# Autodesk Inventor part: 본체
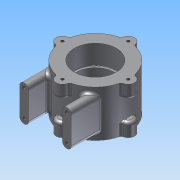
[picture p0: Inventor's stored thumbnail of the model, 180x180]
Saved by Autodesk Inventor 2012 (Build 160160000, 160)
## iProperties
Created: 2015-03
Part Number: 본체
Material: Default
Document SubType Name: Modeling
Designer: net
Density: 1 g/cm^3
Author: net
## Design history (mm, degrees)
sketch "스케치1"
  geometry: C1 r 37 at (0, 0); 1 further point
  constraints: 1 centre point, 1 coincident
  dimensions: "d0" = 74 diameter of C1
extrude "돌출1" new body sketch "스케치1" distance "d1" = 52; taper "d2" = 0 deg
sketch "스케치2"
  geometry: C1 r 7 at (0, 37); C2 r 7 at (-37, 0); C3 r 7 at (0, -37); C4 r 7 at (37, 0); 1 further point
  constraints: 4 centre point, 2 vertical alignment, 10 other
  dimensions: "d3" = 14 diameter of C1; "d6" = 360 deg dimension on point (0, 0) C1.centre (derived)
extrude "돌출2" join sketch "스케치2" distance "d8" = 15; taper "d9" = 0 deg
node "작업 평면1"
hole "구멍1" diameter "d12" = 42; stored, may be unused: countersink angle "d16" = 90 deg, drill point angle "d18" = 118 deg; dims "d10" = 10, "d11" = 10, "d13" = 6, "d14" = 47, "d15" = 22, "d17" = 8
hole "구멍2" diameter "d21" = 42; stored, may be unused: countersink angle "d25" = 90 deg, drill point angle "d27" = 118 deg; dims "d19" = 10, "d20" = 10, "d22" = 6, "d23" = 47, "d24" = 22, "d26" = 8
node "작업 평면2"
sketch "스케치4"
  geometry: L1 (6.969, 15)-(6.969, 0) reference; L2 (36.338, 0)-(6.969, 0) reference; L3 (36.338, 0)-(36.338, 15) reference; L4 (36.338, 15)-(36.338, 15) reference; L5 (36.338, 15)-(36.338, 0) reference; L6 (6.969, 0)-(36.338, 0) reference; L7 (6.969, 0)-(6.969, 15) reference; L8 (6.969, 15)-(-6.969, 15) reference; L9 (-6.969, 15)-(-6.969, 0) reference; L10 (-36.338, 0)-(-6.969, 0) reference; L11 (-36.338, 0)-(-36.338, 15) reference; L12 (-36.338, 15)-(-36.338, 15) reference; L13 (-36.338, 15)-(-36.338, 0) reference; L14 (-6.969, 0)-(-36.338, 0) reference; L15 (-6.969, 0)-(-6.969, 15) reference; L16 (-6.969, 15)-(6.969, 15) reference; L17 (6.969, 52)-(6.969, 37) reference; L18 (6.969, 37)-(-6.969, 37) reference; L19 (-6.969, 37)-(-6.969, 52) reference; L20 (-6.969, 52)-(-36.338, 52) reference; L21 (-36.338, 52)-(-36.338, 37) reference; L22 (-36.338, 37)-(-36.338, 37) reference; L23 (-36.338, 37)-(-36.338, 52) reference; L24 (-36.338, 52)-(-6.969, 52) reference; L25 (-6.969, 52)-(-6.969, 37) reference; L26 (-6.969, 37)-(6.969, 37) reference; L27 (6.969, 37)-(6.969, 52) reference; L28 (6.969, 52)-(36.338, 52) reference; L29 (36.338, 52)-(36.338, 37) reference; L30 (36.338, 37)-(36.338, 37) reference; L31 (36.338, 37)-(36.338, 52) reference; L32 (36.338, 52)-(6.969, 52) reference; L33 (0, 37)-(0, 15); L34 (0, 26)-(-24, 26); L35 (-24, 26)-(-24, 46); L36 (-24, 46)-(-24, 41); L37 (-24, 26)-(-24, 11); L38 (-19, 41)-(-19, 11); L39 (-29, 41)-(-29, 11); A1 r 5 centre (-24, 41) between (-19, 41) and (-29, 41); A2 r 5 centre (-24, 11) between (-19, 11) and (-29, 11); 1 further point
  constraints: 14 end point, 4 point on circle, 3 midpoint, 2 centre point, 2 coincident, 2 horizontal alignment, 2 perpendicular, 2 tangent, 1 collinear, 1 point on line
  dimensions: "d29" = 24 distance of L34.start L34.end; "d30" = 20 distance of L34.end L35.end; "d31" = 5 distance of L35.end L36.end; "d32" = 10 diameter of A1; "d33" = 15 distance of L34.end L37.end; "d34" = 10 diameter of A2; "d35" = 30 distance of L38.start L38.end
extrude "돌출3" join sketch "스케치4" stored distance "d36" = 15; taper "d37" = 0 deg
hole "구멍3" diameter "d40" = 3.242; stored, may be unused: countersink angle "d44" = 90 deg, drill point angle "d46" = 118 deg; dims "d38" = 10, "d39" = 10, "d41" = 8, "d42" = 47, "d43" = 22, "d45" = 11
node "작업 평면3"
sketch "스케치5"
  geometry: L1 (53, 30)-(53, 0) reference; L2 (43, 0)-(43, 30) reference; A1 r 5 centre (0, 0) between (-5, 0) and (5, 0) reference; A2 r 5 centre (0, 30) between (5, 30) and (-5, 30) reference; A3 r 5 centre (48, 0) between (43, 0) and (53, 0) reference; A4 r 5 centre (48, 30) between (53, 30) and (43, 30) reference; 5 further points
  constraints: 4 coincident
hole "구멍4" sketch "스케치5" at (0, 30), (0, 0), (48, 30), (48, 0) diameter "d50" = 4.134; stored, may be unused: countersink angle "d54" = 90 deg, drill point angle "d56" = 118 deg; dims "d51" = 6, "d52" = 47, "d53" = 22, "d55" = 8
node "작업 평면4"
sketch "스케치6"
  geometry: L1 (0, 0)-(-37, 0); L2 (0, 0)-(-26.163, 26.163); C1 r 1.621 at (37, 0) reference; C2 r 1.621 at (0, -37) reference; C3 r 1.621 at (-37, 0) reference; C4 r 1.621 at (0, 37) reference; C5 r 23.5 at (0, 0) reference; A1 r 37 centre (0, 0) between (36.338, 6.969) and (6.969, 36.338) reference; A2 r 7 centre (37, 0) between (36.338, -6.969) and (36.338, 6.969) reference; A3 r 37 centre (0, 0) between (6.969, -36.338) and (36.338, -6.969) reference; A4 r 7 centre (0, -37) between (-6.969, -36.338) and (6.969, -36.338) reference; A5 r 37 centre (0, 0) between (-36.338, -6.969) and (-6.969, -36.338) reference; A6 r 7 centre (-37, 0) between (-36.338, 6.969) and (-36.338, -6.969) reference; A7 r 37 centre (0, 0) between (-6.969, 36.338) and (-36.338, 6.969) reference; A8 r 7 centre (0, 37) between (6.969, 36.338) and (-6.969, 36.338) reference; 1 further point
  constraints: 4 end point, 1 horizontal, 1 point on circle
  dimensions: "d57" = 45 deg angle of L1 L2
  node "투영된 루프3"
node "작업 평면5"
sketch "스케치8"
  geometry: L1 (36.754, -15)-(36.754, 15) reference; L2 (35.885, 15)-(35.885, -15) reference; L3 (9.015, -15)-(9.015, 15) reference; L4 (-4.258, 15)-(-4.258, -15) reference; L5 (-20.767, -11)-(-20.767, -26) reference; L6 (20.767, -26)-(-20.767, -26) reference; L7 (20.767, -26)-(20.767, -11) reference; L8 (20.767, -11)-(30.622, -11) reference; L9 (30.622, -11)-(30.622, -26) reference; L10 (30.622, -26)-(30.622, -26) reference; L11 (30.622, -26)-(30.622, -11) reference; L12 (30.622, -11)-(20.767, -11) reference; L13 (20.767, -11)-(20.767, -26) reference; L14 (-20.767, -26)-(20.767, -26) reference; L15 (-20.767, -26)-(-20.767, -11) reference; L16 (-20.767, -11)-(-30.622, -11) reference; L17 (-30.622, -11)-(-30.622, -26) reference; L18 (-30.622, -26)-(-30.622, -26) reference; L19 (-30.622, -26)-(-30.622, -11) reference; L20 (-30.622, -11)-(-20.767, -11) reference; L21 (-20.767, 26)-(-20.767, 11) reference; L22 (-20.767, 11)-(-30.622, 11) reference; L23 (-30.622, 11)-(-30.622, 26) reference; L24 (-30.622, 26)-(-30.622, 26) reference; L25 (-30.622, 26)-(-30.622, 11) reference; L26 (-30.622, 11)-(-20.767, 11) reference; L27 (-20.767, 11)-(-20.767, 26) reference; L28 (-20.767, 26)-(20.767, 26) reference; L29 (20.767, 26)-(20.767, 11) reference; L30 (20.767, 11)-(30.622, 11) reference; L31 (30.622, 11)-(30.622, 26) reference; L32 (30.622, 26)-(30.622, 26) reference; L33 (30.622, 26)-(30.622, 11) reference; L34 (30.622, 11)-(20.767, 11) reference; L35 (20.767, 11)-(20.767, 26) reference; L36 (20.767, 26)-(-20.767, 26) reference; 3 further points
  constraints: 4 horizontal alignment, 1 coincident, 1 other
feature "엠보싱1" sketch "스케치8" dims "d10" = 10, "d11" = 10, "d58" = 0.5, "d59" = 0
fillet "모깎기1" dims "d60" = 0.3
fillet "모깎기2" dims "d61" = 3
node "솔리드1"
mirror "대칭1"
mirror "대칭2"
pattern_circular "원형 패턴1" dims angle "d48" = 360 deg
mirror "대칭3"
node "투영된 루프1"
node "투영된 루프2"
node "투영된 루프4"
other parameters: "d28" = -56
